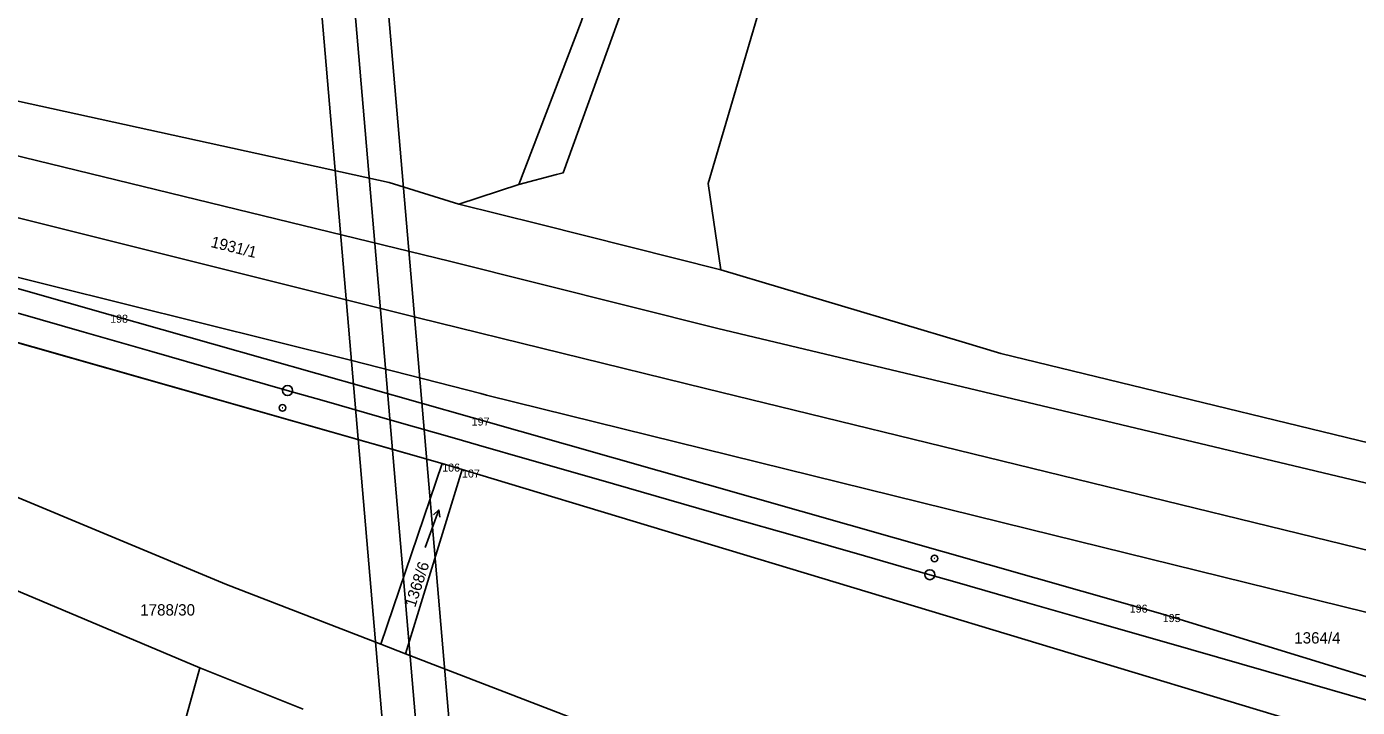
# Model space of a CAD drawing. Extents: x -779330 to -774454, y -1144748 to -1142831.
# Drawn here: x -777612.9 to -777413.3, y -1143734.5 to -1143632.3 of the extents above; entities that cross this region are included whole.
import ezdxf

# ---------------------------------------------------------------- set-up
doc = ezdxf.new("R2010")
doc.units = 0
for name, color, linetype in [('Hranice parcel', 7, 'Continuous'), ('Parcelní čísla', 7, 'Continuous'), ('SŽDC', 7, 'Continuous'), ('Vnitřní kresba', 7, 'Continuous'), ('Vrstva 1', 7, 'Continuous'), ('Vrstva 53', 7, 'Continuous'), ('Vrstva 60', 7, 'Continuous'), ('Vrstva 7', 7, 'Continuous'), ('Značky kultur', 7, 'Continuous')]:
    doc.layers.add(name, color=color, linetype=linetype)

msp = doc.modelspace()

# ---------------------------------------------------------------- linework, layer by layer
at = {"layer": 'Hranice parcel'}
for p, q in [((-777548.1, -1143658.97), (-777539.12, -1143656)), ((-777550.6, -1143697.9), (-777622.38, -1143677.44)), ((-777550.6, -1143697.9), (-777559.79, -1143725)), ((-777547.63, -1143698.79), (-777550.6, -1143697.9)), ((-777547.63, -1143698.79), (-777556.08, -1143726.43)), ((-777442.54, -1143720.48), (-777400.53, -1143733.41)), ((-777556.08, -1143726.43), (-777559.79, -1143725)), ((-777586.96, -1143728.55), (-777628.63, -1143877.96)), ((-777586.96, -1143728.55), (-777571.45, -1143734.73))]:
    msp.add_line(p, q, dxfattribs=at)
for points in [[(-777508.79, -1143668.8), (-777510.73, -1143655.88), (-777497.53, -1143610.93), (-777481.94, -1143562.57), (-777470.6, -1143527.36), (-777466.94, -1143516.02), (-777464.9, -1143509.68)], [(-777496.86, -1143535.74), (-777517.68, -1143596.22), (-777520.04, -1143603.06), (-777529.74, -1143631.58), (-777539.12, -1143656)], [(-777539.12, -1143656), (-777533.45, -1143654.53), (-777532.48, -1143654.28), (-777515.5, -1143607.29), (-777513.98, -1143602.78), (-777492.04, -1143537.65)], [(-778102.74, -1143613.61), (-778067.87, -1143604.7), (-778036.9, -1143597.86), (-777971.64, -1143592.01), (-777964.3, -1143591.17), (-777890.59, -1143590.67), (-777860.75, -1143594.87), (-777857.58, -1143595.32), (-777803.43, -1143602.93), (-777799.69, -1143603.46), (-777791.04, -1143604.67), (-777558.56, -1143655.7), (-777548.1, -1143658.97)], [(-777375.98, -1143729.1), (-777462.56, -1143707.72), (-777543.96, -1143687.61), (-777544.8, -1143687.4), (-777564.35, -1143682.38), (-777643.12, -1143662.79), (-777672.41, -1143655.46), (-777784.28, -1143627.47), (-777786.92, -1143627.45)], [(-777716.22, -1143651.23), (-777687.78, -1143654.61), (-777659.91, -1143659.97), (-777643.37, -1143663.67), (-777619.92, -1143670.03), (-777600.4, -1143675.56)], [(-777548.1, -1143658.97), (-777536, -1143661.99), (-777508.79, -1143668.8)], [(-777773.53, -1143661.8), (-777723.87, -1143663.43), (-777711.36, -1143665.84), (-777650.39, -1143687.95), (-777582.96, -1143716.06), (-777559.79, -1143725)], [(-777371.14, -1143700.16), (-777375.2, -1143699.98), (-777393.58, -1143699.19), (-777466.8, -1143681.38), (-777472.61, -1143679.64), (-777508.79, -1143668.8)], [(-777586.96, -1143728.55), (-777654.9, -1143699.9), (-777700.17, -1143683.78), (-777725.33, -1143676.3), (-777780.89, -1143673.92), (-777815.03, -1143678.47)], [(-777600.4, -1143675.56), (-777546.18, -1143690.99), (-777447.49, -1143719.07), (-777442.54, -1143720.48)], [(-777358.14, -1143760.61), (-777362.08, -1143759.74), (-777364.95, -1143754.01), (-777547.63, -1143698.79)], [(-777375.94, -1143800.75), (-777415.86, -1143782.49), (-777462.27, -1143762.62), (-777556.08, -1143726.43)]]:
    msp.add_lwpolyline(points, dxfattribs=at)
at = {"layer": 'SŽDC'}
for points in [[(-777130.76, -1143810.13), (-777274.26, -1143769.36), (-777322.71, -1143754.8), (-777354.97, -1143745.11), (-777360.64, -1143743.54), (-777364.22, -1143742.54), (-777366.62, -1143741.88), (-777370.73, -1143741.3), (-777400.53, -1143733.41), (-777442.54, -1143720.48), (-777447.49, -1143719.07), (-777546.18, -1143690.99), (-777600.4, -1143675.56), (-777619.92, -1143670.03)], [(-777622.38, -1143677.44), (-777550.6, -1143697.9), (-777547.63, -1143698.79), (-777364.95, -1143754.01), (-777362.08, -1143759.74), (-777358.14, -1143760.61), (-777354.56, -1143760.13), (-777348.72, -1143768.82), (-777340.59, -1143770.61)]]:
    msp.add_lwpolyline(points, dxfattribs=at)
at = {"layer": 'Vnitřní kresba'}
for p, q in [((-777664.65, -1143639.46), (-777549.5, -1143667.53)), ((-777554.18, -1143676), (-777668.6, -1143647.45)), ((-777509.28, -1143677.62), (-777549.5, -1143667.53)), ((-777511.09, -1143686.61), (-777554.18, -1143676)), ((-777509.28, -1143677.62), (-777391.49, -1143705.71)), ((-777511.09, -1143686.61), (-777400.48, -1143713.69))]:
    msp.add_line(p, q, dxfattribs=at)
at = {"layer": 'Vrstva 1'}
for points in [[(-777571, -1143485.76), (-778617.18, -1143575.21), (-778591.88, -1143871.12), (-777545.7, -1143781.67)], [(-777551.11, -1143777.12), (-778587.32, -1143865.71), (-778611.77, -1143579.77), (-777575.56, -1143491.17)], [(-777580.11, -1143496.57), (-778407.09, -1143567.28), (-778383.5, -1143843.27), (-777556.51, -1143772.57)]]:
    msp.add_lwpolyline(points, close=True, dxfattribs=at)
msp.add_lwpolyline([(-777408.97, -1143734.24), (-777420.06, -1143731.06), (-777430.69, -1143728), (-777441.98, -1143724.76), (-777451.96, -1143721.89), (-777462.83, -1143718.78), (-777473.72, -1143715.65), (-777477.48, -1143714.57), (-777487.28, -1143711.76), (-777497.37, -1143708.86), (-777507.6, -1143705.92), (-777516.61, -1143703.33), (-777526.83, -1143700.4), (-777537.5, -1143697.33), (-777545.14, -1143695.15), (-777548.77, -1143694.1), (-777557.76, -1143691.53), (-777568.3, -1143688.5), (-777573.86, -1143686.91), (-777584.11, -1143683.97), (-777594.17, -1143681.08), (-777604.31, -1143678.17), (-777614.21, -1143675.34)], dxfattribs=at)
at = {"layer": 'Vrstva 53'}
for points in [[(-777619.92, -1143670.03), (-777600.4, -1143675.56), (-777546.18, -1143690.99), (-777447.49, -1143719.07), (-777442.54, -1143720.48), (-777400.53, -1143733.41), (-777370.73, -1143741.3), (-777366.62, -1143741.88), (-777364.22, -1143742.54), (-777360.64, -1143743.54), (-777354.97, -1143745.11), (-777322.71, -1143754.8), (-777274.26, -1143769.36), (-777130.76, -1143810.13)], [(-777619.92, -1143670.03), (-777600.4, -1143675.56), (-777546.18, -1143690.99), (-777447.49, -1143719.07), (-777442.54, -1143720.48), (-777400.53, -1143733.41), (-777370.73, -1143741.3), (-777366.62, -1143741.88), (-777364.22, -1143742.54), (-777360.64, -1143743.54), (-777354.97, -1143745.11), (-777322.71, -1143754.8), (-777274.26, -1143769.36), (-777130.76, -1143810.13)], [(-777340.59, -1143770.61), (-777348.72, -1143768.82), (-777354.56, -1143760.13), (-777358.14, -1143760.61), (-777362.08, -1143759.74), (-777364.95, -1143754.01), (-777547.63, -1143698.79), (-777550.6, -1143697.9), (-777622.38, -1143677.44)], [(-777340.59, -1143770.61), (-777348.72, -1143768.82), (-777354.56, -1143760.13), (-777358.14, -1143760.61), (-777362.08, -1143759.74), (-777364.95, -1143754.01), (-777547.63, -1143698.79), (-777550.6, -1143697.9), (-777622.38, -1143677.44)]]:
    msp.add_lwpolyline(points, dxfattribs=at)
at = {"layer": 'Vrstva 60'}
for p, q in [((-777600.4, -1143675.56), (-777600.4, -1143675.56)), ((-777546.18, -1143690.99), (-777546.18, -1143690.99)), ((-777550.6, -1143697.9), (-777550.6, -1143697.9)), ((-777547.63, -1143698.79), (-777547.63, -1143698.79)), ((-777447.49, -1143719.07), (-777447.49, -1143719.07)), ((-777442.54, -1143720.48), (-777442.54, -1143720.48))]:
    msp.add_line(p, q, dxfattribs=at)
at = {"layer": 'Vrstva 7'}
for p, q in [((-777574.5, -1143689.55), (-777574.59, -1143689.52)), ((-777476.71, -1143712.14), (-777476.81, -1143712.11))]:
    msp.add_line(p, q, dxfattribs=at)
for centre, radius in [((-777573.79, -1143686.93), 0.75), ((-777574.55, -1143689.54), 0.5), ((-777476.76, -1143712.13), 0.5), ((-777477.47, -1143714.57), 0.75)]:
    msp.add_circle(centre, radius, dxfattribs=at)
at = {"layer": 'Značky kultur'}
for p, q in [((-777553.14, -1143710.48), (-777551.09, -1143704.84)), ((-777551.09, -1143704.84), (-777551.9, -1143705.58)), ((-777551.09, -1143704.84), (-777550.95, -1143705.93))]:
    msp.add_line(p, q, dxfattribs=at)

# ---------------------------------------------------------------- texts
at = {"layer": 'Parcelní čísla'}
for s, rotation, p in [('1931/1', 346, (-777585.41, -1143665.38)), ('1368/6', 72, (-777554.66, -1143719.57))]:
    msp.add_text(s, height=1.7, rotation=rotation, dxfattribs=at).set_placement(p)
for s, p in [('1788/30', (-777595.89, -1143720.7)), ('1364/4', (-777422.82, -1143724.9))]:
    msp.add_text(s, height=1.7, dxfattribs=at).set_placement(p)
at = {"layer": 'Vrstva 60'}
for s, p in [('198', (-777600.4, -1143676.76)), ('197', (-777546.18, -1143692.19)), ('106', (-777550.6, -1143699.1)), ('107', (-777547.63, -1143699.99)), ('196', (-777447.49, -1143720.27)), ('195', (-777442.54, -1143721.68))]:
    msp.add_text(s, height=1.2, dxfattribs=at).set_placement(p)

doc.saveas('drawing.dxf')
